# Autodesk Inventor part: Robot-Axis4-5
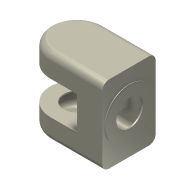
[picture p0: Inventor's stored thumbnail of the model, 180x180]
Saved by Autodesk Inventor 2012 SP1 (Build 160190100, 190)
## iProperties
Shininess: 21.0
Length Units: 11269
Angle Units: 11279
Time Units: 11290
Mass Units: 11283
Length Display Precision: 3
Angle Display Precision: 2
Created: 2001-08
Part Number: Robot-Axis4-5
Document SubType Name: ﾓﾃﾞﾘﾝｸﾞ
Designer: Administrator
Density: 1 g/cm^3
Material: Default
Density: 0.0
Volumn: 0.0
Area: 0.0
PropertySet Name: Model Information
Control State: 0
Master: False
Checked Out: False
Author: Administrator
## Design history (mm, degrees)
sketch "ｽｹｯﾁ1"
  geometry: L1 (0, -40)-(-118, -40); L2 (-118, -40)-(-118, 40); L3 (-118, 40)-(0, 40); L4 (0, 40)-(0, -40); L5 (-118, 0)-(0, 0); L6 (-78, 40)-(-78, -40); 2 further points
  constraints: 12 end point, 4 point on line, 3 midpoint, 2 horizontal, 2 parallel, 1 perpendicular, 1 vertical, 1 vertical alignment, 3 other
  dimensions: "d0" = 80 distance of L1.end L2.end; "d1" = 118 distance of L2.end L3.end
extrude "押し出し1" new body sketch "ｽｹｯﾁ1" stored distance "d2" = 116; taper "d3" = 0 deg
node "作業平面1"
sketch "ｽｹｯﾁ2"
  geometry: L1 (0, 40)-(-78, 40) reference; L2 (-78, -40)-(0, -40) reference; L3 (-38, 40)-(-38, -40); C1 r 40 at (-78, 0); A1 r 40 centre (-78, 0) between (-78, 40) and (-78, -40) reference
  constraints: 2 end point, 2 point on line, 1 centre point, 1 coincident, 1 concentric, 1 perpendicular, 1 tangent
extrude "押し出し2" cut sketch "ｽｹｯﾁ2" stored distance "d4" = 50; taper "d5" = 0 deg
sketch "ｽｹｯﾁ3"
  geometry: L1 (0, 0)-(0, 60) reference; L2 (-116, 60)-(-116, 0) reference; L3 (-116, 30)-(0, 30); L4 (-33, 70)-(-83, 70) reference; L5 (-58, 70)-(-58, -10); L6 (-83, -10)-(-33, -10) reference; C1 r 37 at (-58, 30)
  constraints: 5 midpoint, 4 end point, 1 centre point
  dimensions: "d7" = 74 diameter of C1
extrude "押し出し3" join sketch "ｽｹｯﾁ3" distance "d8" = 1; taper "d9" = 0 deg
node "作業軸1"
shell "Shell1" dims "d10" = 2
sketch "Sketch4"
  geometry: C1 r 37 at (0, 0) reference
hole "Hole1" sketch "Sketch4" at (0, 0) diameter "d11" = 40; stored, may be unused: countersink angle "d15" = 82 deg, drill point angle "d17" = 118 deg; dims "d12" = 6, "d13" = 4, "d14" = 2, "d16" = 2
sketch "Sketch5"
  geometry: A1 r 40 centre (-78, 0) between (-78, 40) and (-78, -40) reference
hole "Hole2" sketch "Sketch5" at (-78, 0) diameter "d18" = 40; stored, may be unused: countersink angle "d22" = 82 deg, drill point angle "d24" = 118 deg; dims "d19" = 6, "d20" = 4, "d21" = 2, "d23" = 2
sketch "Sketch6"
  geometry: A1 r 40 centre (78, 0) between (78, -40) and (78, 40) reference
hole "Hole3" sketch "Sketch6" at (78, 0) diameter "d25" = 40; stored, may be unused: countersink angle "d29" = 82 deg, drill point angle "d31" = 118 deg; dims "d26" = 6, "d27" = 4, "d28" = 2, "d30" = 2
body "Solid1"
fillet "Fillet1" dims "d6" = 10
